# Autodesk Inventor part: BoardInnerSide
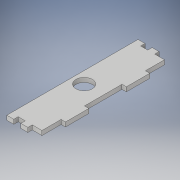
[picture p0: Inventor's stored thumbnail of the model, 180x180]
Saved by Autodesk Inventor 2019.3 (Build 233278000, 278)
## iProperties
Created: 2020-03
Part Number: BoardInnerSide
Material: Generic
Document SubType Name: Modeling
Designer: KrystynWikoff
Density: 1 g/cm^3
Appearance: Default
Author: KrystynWikoff
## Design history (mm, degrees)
sketch "Sketch1"
  geometry: L1 (0, 0)-(19.05, 0); L2 (19.05, 0)-(19.05, -71.1); L3 (19.05, -71.1)-(0, -71.1); L4 (0, -71.1)-(0, 0)
  constraints: 8 end point, 2 parallel, 1 horizontal, 1 perpendicular
  dimensions: "d0" = 19.05 distance of L2.end L3.end; "d1" = 71.1 distance of L1.end L2.end
extrude "Extrusion1" new body sketch "Sketch1" distance "d2" = 2.3622; taper "d3" = 0 deg
sketch "Sketch4" dims "d44" = 25.4
  geometry: L1 (-3.81, 0)-(-7.62, 0); L2 (-7.62, 0)-(-7.62, 2.362); L3 (-7.62, 2.362)-(-3.81, 2.362); L4 (-3.81, 2.362)-(-3.81, 0); L5 (0, 0)-(0, 71.1) reference; L6 (-19.05, 0)-(0, 0) reference; L7 (-11.43, 0)-(-15.24, 0); L8 (-15.24, 0)-(-15.24, 2.362); L9 (-15.24, 2.362)-(-11.43, 2.362); L10 (-11.43, 2.362)-(-11.43, 0); L11 (-3.81, 0)-(0, 0); L12 (0, 0)-(0, 2.362); L13 (0, 2.362)-(-3.81, 2.362); L14 (-3.81, 2.362)-(-3.81, 0); L15 (0, 71.1)-(-3.81, 71.1); L16 (-3.81, 71.1)-(-3.81, 68.738); L17 (-3.81, 68.738)-(0, 68.738); L18 (0, 68.738)-(0, 71.1); L19 (0, 71.1)-(-19.05, 71.1) reference; L20 (-3.81, 68.738)-(-7.62, 68.738); L21 (-7.62, 68.738)-(-7.62, 71.1); L22 (-7.62, 71.1)-(-3.81, 71.1); L23 (-3.81, 71.1)-(-3.81, 68.738); L24 (-11.43, 71.1)-(-15.24, 71.1); L25 (-15.24, 71.1)-(-15.24, 68.738); L26 (-15.24, 68.738)-(-11.43, 68.738); L27 (-11.43, 68.738)-(-11.43, 71.1)
  constraints: 48 end point, 10 parallel, 6 horizontal, 5 perpendicular, 3 point on line, 1 collinear, 7 other
  dimensions: "d35" = 3.81 distance of L2.end L3.end; "d36" = 3.81 distance between parallel lines of L5 L4; "d37" = 2.3622 distance of L1.end L2.end; "d38" = 0 distance between parallel lines of L6 L1; "d41" = 7.62 distance of L1.start L7.start; "d46" = 2.3622 distance of L11.end L12.end; "d47" = 3.81 distance of L16.end L17.end; "d48" = 2.3622 distance of L15.end L16.end; "d49" = 3.81 distance of L16.end L20.end; "d50" = 3.81 distance of L25.end L26.end; "d51" = 2.3622 distance of L26.end L24.start; "d52" = 3.81 distance between parallel lines of L21 L27
extrude "Extrusion4" cut sketch "Sketch4" distance "d53" = 25.4; taper "d54" = 0 deg
sketch "Sketch5"
  geometry: L1 (0, 0)-(-2.362, 0); L2 (-2.362, 0)-(-2.362, 12.7); L3 (-2.362, 12.7)-(0, 12.7); L4 (0, 12.7)-(0, 0); L5 (0, 71.1)-(-2.362, 71.1); L6 (-2.362, 71.1)-(-2.362, 58.4); L7 (-2.362, 58.4)-(0, 58.4); L8 (0, 58.4)-(0, 71.1); L9 (-7.62, 71.1)-(-11.43, 71.1) reference; L10 (0, 2.362)-(0, 68.738) reference; L11 (0, 25.4)-(-2.362, 25.4); L12 (-2.362, 25.4)-(-2.362, 45.7); L13 (-2.362, 45.7)-(0, 45.7); L14 (0, 45.7)-(0, 25.4)
  constraints: 24 end point, 6 parallel, 3 horizontal, 3 perpendicular, 1 point on line
  dimensions: "d55" = 12.7 distance of L1.end L2.end; "d56" = 2.3622 distance of L1.start L1.end; "d57" = 0 distance between parallel lines of L5 L9; "d58" = 12.7 distance of L5.end L6.end; "d59" = 2.3622 distance of L6.end L7.end; "d60" = 2.3622 distance between parallel lines of L10 L6; "d61" = 12.7 distance between parallel lines of L3 L11; "d62" = 12.7 distance between parallel lines of L7 L13; "d63" = 2.3622 distance of L11.start L11.end
extrude "Extrusion5" cut sketch "Sketch5" distance "d64" = 25.4; taper "d65" = 0 deg
sketch "Sketch6"
  geometry: L1 (0, 12.7)-(0, 25.4) reference; L2 (-19.05, 0)-(-15.24, 0) reference; C1 r 4.445 at (-12.7, 35.547); 1 further point
  constraints: 1 centre point
  dimensions: "d66" = 12.7 distance from line of L1 C1.centre; "d67" = 8.89 diameter of C1; "d68" = 35.5473 distance from line of L2 C1.centre
extrude "Extrusion6" cut sketch "Sketch6" distance "d69" = 25.4; taper "d70" = 0 deg
body "Solid1"
